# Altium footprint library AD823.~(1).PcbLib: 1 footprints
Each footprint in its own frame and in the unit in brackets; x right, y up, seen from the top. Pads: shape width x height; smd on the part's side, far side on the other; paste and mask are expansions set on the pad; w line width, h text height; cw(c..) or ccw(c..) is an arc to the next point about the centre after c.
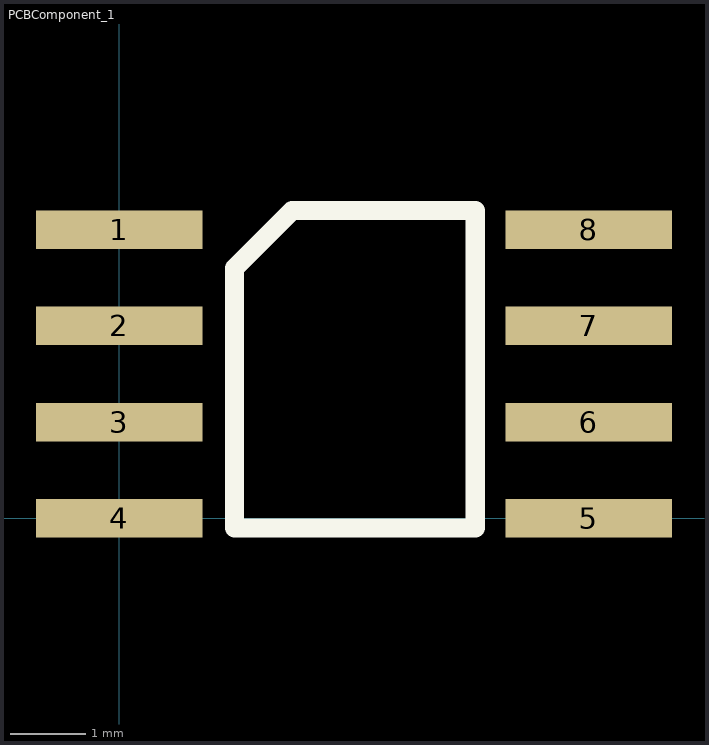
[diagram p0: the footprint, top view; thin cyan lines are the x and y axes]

## PCBComponent_1 [mm]
pads (8):
  rect 2.2x0.51 all layers, no hole: 1(0,3.81) 2(0,2.54) 3(0,1.27) 4(0,0) 5(6.2,0) 6(6.2,1.27) 7(6.2,2.54) 8(6.2,3.81)
Top Overlay:
  lines w0.254: 1.524,-0.127 4.699,-0.127 4.699,4.064 2.413,4.064 2.286,4.064 1.524,3.302 1.524,-0.127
